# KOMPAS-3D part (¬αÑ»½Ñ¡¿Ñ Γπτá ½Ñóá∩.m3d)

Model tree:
1. Эскиз:1
2. Операция выдавливания:1
     Расстояние 1 = 1
3. Эскиз:2
4. Операция выдавливания:2
     Расстояние 1 = 6
5. Эскиз:3
6. Операция выдавливания:3
     Расстояние 1 = 2
7. Эскиз:4
8. Операция выдавливания:4
     Расстояние 1 = 6
9. Эскиз:5
10. Операция выдавливания:5
     Расстояние 1 = 1
11. Эскиз:8
12. Вырезать элемент выдавливания:3
     Расстояние 1 = 11
13. Эскиз:9
14. Вырезать элемент выдавливания:4
     Расстояние 1 = 8.37004
15. Эскиз:10
16. Вырезать элемент выдавливания:5
     Расстояние 1 = 11.665
17. Эскиз:11
18. Вырезать элемент выдавливания:6
     Расстояние 1 = 7.28161

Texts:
  крепление туча левая
  Сплав АЛ8  ГОСТ 1583-93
